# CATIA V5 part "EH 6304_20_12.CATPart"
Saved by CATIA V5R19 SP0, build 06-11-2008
Definition: EH 6304_20_12
Nomenclature: EH 6304_20_12
Description: PART--DESC
Material "Steel": density 7860 kg/m3, Young's modulus 2e+11 Pa, Poisson ratio 0.266, thermal expansion 1.17e-05 1/K
Bounding box of the stored display mesh (mm): x -165.2 to -109.5, y 99 to 121, z 56.01 to 77.99
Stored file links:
  G:\UTB\Kombinované\Bakalářská práce\Catia\FORMA\EH 6304_20_12.CATPart
  D:\Aplikace\CATIA\Nová složka\win_b64\startup\materials\Catalog.CATMaterial
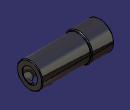
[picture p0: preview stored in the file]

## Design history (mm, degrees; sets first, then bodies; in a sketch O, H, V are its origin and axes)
Body1 "EH 6304_20_12" (main body)
  Solid1: solid without history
